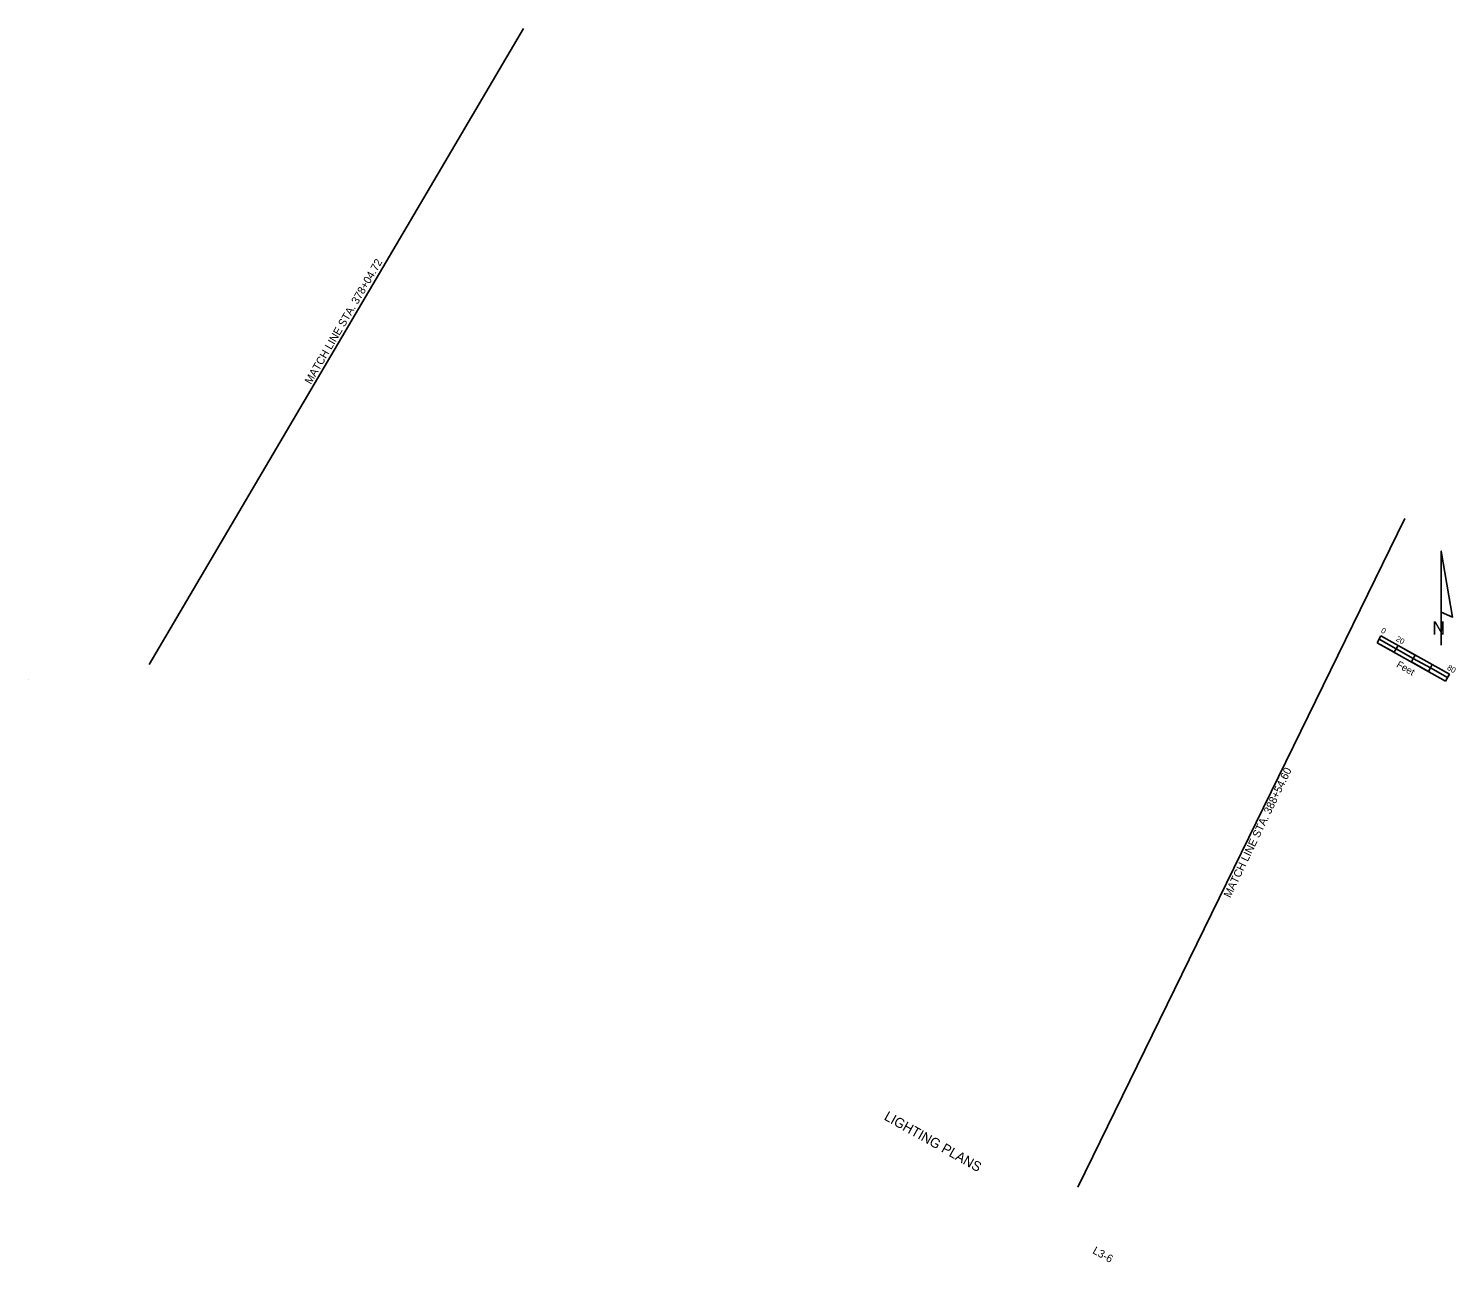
# Model space of a CAD drawing. Extents: x 916075 to 917531, y 637086 to 638344.
import ezdxf

# ---------------------------------------------------------------- set-up
doc = ezdxf.new("R2010")
doc.units = 0
for name, color, linetype in [('CGBack_ep', 7, 'Continuous'), ('CGFace_ep', 7, 'Continuous'), ('ConcSlabs_ep', 7, 'Continuous'), ('PavtConcJoints_ep', 7, 'Continuous'), ('SignMulti_ep', 7, 'Continuous'), ('Slopes_ep', 7, 'Continuous')]:
    doc.layers.add(name, color=color, linetype=linetype)

msp = doc.modelspace()

# ---------------------------------------------------------------- linework, layer by layer
at = {"layer": 'CGBack_ep'}
for p, q in [((916580.1, 638344.1), (916198.4, 637695.6)), ((917479.1, 637844.4), (917145.6, 637162.5))]:
    msp.add_line(p, q, dxfattribs=at)
at = {"layer": 'CGFace_ep'}
msp.add_line((916075.3, 637680.2), (916075.3, 637680.2), dxfattribs=at)
at = {"layer": 'PavtConcJoints_ep'}
msp.add_line((917516.2, 637715.1), (917516.2, 637811.1), dxfattribs=at)
msp.add_lwpolyline([(917516.2, 637748.7), (917516.2, 637811.1), (917527.7, 637743.9)], close=True, dxfattribs=at)
at = {"layer": 'SignMulti_ep'}
for p, q in [((917454.7, 637724.7), (917450.8, 637717.7)), ((917450.8, 637717.7), (917520.6, 637678.6)), ((917524.5, 637685.6), (917454.7, 637724.7)), ((917520.6, 637678.6), (917524.5, 637685.6))]:
    msp.add_line(p, q, dxfattribs=at)
for points in [[(917450.8, 637717.7), (917452.7, 637721.2), (917470.2, 637711.4), (917468.2, 637707.9)], [(917470.2, 637711.4), (917472.1, 637714.9), (917489.6, 637705.1), (917487.6, 637701.6)], [(917485.7, 637698.2), (917487.6, 637701.6), (917505.1, 637691.9), (917503.1, 637688.4)], [(917505.1, 637691.9), (917507, 637695.3), (917524.5, 637685.6), (917522.5, 637682.1)]]:
    msp.add_lwpolyline(points, close=True, dxfattribs=at)

# ---------------------------------------------------------------- texts
at = {"layer": 'CGBack_ep'}
for s, rotation, p in [('MATCH LINE STA. 378+04.72', 59.7534, (916363.3, 637980.6)), ('MATCH LINE STA. 388+54.60', 64.3827, (917301, 637456.9))]:
    msp.add_text(s, height=8, rotation=rotation, dxfattribs=at).set_placement(p)
at = {"layer": 'ConcSlabs_ep'}
msp.add_text('        LIGHTING PLANS         ', height=10, rotation=330.7127, dxfattribs=at).set_placement((916921.2, 637246.2))
at = {"layer": 'PavtConcJoints_ep'}
msp.add_text('N', height=13.4, dxfattribs=at).set_placement((917507.1, 637726))
at = {"layer": 'SignMulti_ep'}
for s, height, p in [('0', 5.6, (917454.1, 637728.5)), ('20', 5.6, (917469.3, 637720)), ('Feet', 7.2, (917469.8, 637693.3)), ('80', 5.6, (917521.6, 637690.6))]:
    msp.add_text(s, height=height, rotation=330.7127, dxfattribs=at).set_placement(p)
at = {"layer": 'Slopes_ep'}
msp.add_text(' L3-6 ', height=8, rotation=330.7127, dxfattribs=at).set_placement((917157.3, 637096.8))

doc.saveas('drawing.dxf')
